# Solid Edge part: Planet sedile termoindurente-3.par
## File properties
Author: s.pallini
Template: Normal.par
Last saved by: s.pallini
Revision: 6
Application: Solid Edge
Precisione: 0,990
Tipo di contenuto documento: 0
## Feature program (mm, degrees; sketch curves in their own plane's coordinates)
sketch for "ExtrudedProtrusion_1" plane through (0, 0, 0) normal (0, -1, 0) x-axis (1, 0, 0)
  line (-130, -255) -> (130, -255)
  line (130, -255) -> (130, -177.5528)
  arc centre (210, -177.5528) radius 80 from (148.9091, -125.9011) to (130, -177.5528) ccw
  arc centre (-210, -177.5528) radius 80 from (-130, -177.5528) to (-148.9091, -125.9011) ccw
  line (-130, -255) -> (-130, -177.5528)
  dimension (linear) = 130
extrude "ExtrudedProtrusion_1" add finite 50 along -normal
draft "Draft_1"  Angles1 = 10 deg
thinwall "Thinwall_1"  Thickness = 5 mm
fillet "Rotondo_1" radius 5
fillet "Rotondo_2" radius 3
sketch for "ExtrudedProtrusion_2" #1 plane through (0, 5, -36.5059) normal (0, 1, 0) x-axis (-1, 0, 0)
  line (11.9982, -218.4941) -> (11.9982, -188.4941)
  line (11.9982, -188.4941) -> (46.9982, -188.4941)
  line (46.9982, -188.4941) -> (46.9982, -218.4941)
  line (46.9982, -218.4941) -> (11.9982, -218.4941)
sketch for "ExtrudedProtrusion_2" #2 plane through (0, 5, -36.5059) normal (0, 1, 0) x-axis (-1, 0, 0)
  line (-47.0018, -218.4941) -> (-47.0018, -188.4941)
  line (-47.0018, -188.4941) -> (-12.0018, -188.4941)
  line (-12.0018, -188.4941) -> (-12.0018, -218.4941)
  line (-12.0018, -218.4941) -> (-47.0018, -218.4941)
  dimension (linear) = 47.0018
extrude "ExtrudedProtrusion_2" add finite 35 along +normal
fillet "Rotondo_3" radius 15
sketch for "ExtrudedProtrusion_3" #1 plane through (0, 5, -36.5059) normal (0, 1, 0) x-axis (0, 0, -1)
sketch for "ExtrudedProtrusion_3" #2 plane through (0, 5, -36.5059) normal (0, 1, 0) x-axis (0, 0, -1)
extrude "ExtrudedProtrusion_3" add finite 15 along +normal
fillet "Rotondo_4" radius 5
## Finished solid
Body 1: solid body, 45 faces, 101 edges, 58 vertices.
  Faces by surface: plane 16, torus 12, cylinder 11, cone 6
  Edges by curve: line 51, circle 48, ellipse 2
Bounding box of the edges (mm; curved faces can reach further): 388.758 x 50.000 x 449.379, from (-194.3792, 0, -255) to (194.3792, 50, 194.3792).
Cylindrical faces by radius (mm): R3 x5, R5 x2, R7.5 x2, R15 x2
Conical faces (half-angle, radius in mm at the cone's reference point): 10 deg R80 x2, 10 deg R84.924 x2, 10 deg R190.076 x1, 10 deg R195 x1
Toroidal faces (ring radius, tube radius in mm): R2 r3 x2, R2.5 r5 x2, R12.5 r5 x2, R83.5753 r3 x2, R93.0118 r5 x2, R181.9882 r5 x1, R191.4247 r3 x1
Planar faces by outward normal: +x 2, +y 4, +z 2, -x 2, -y 1, -z 1, oblique 4
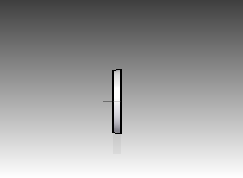
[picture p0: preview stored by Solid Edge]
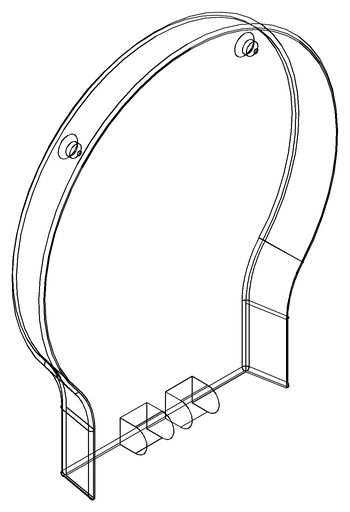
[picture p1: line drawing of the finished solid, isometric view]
